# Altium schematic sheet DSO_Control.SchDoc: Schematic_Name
size A4; CompanyName: University of Melbourne; Engineer: Your Name Here; DocumentNumber: 1; Revision: 0.1; SheetNumber: 1; SheetTotal: 1; Title_Project: Project_Title; StudentNo: Student No.
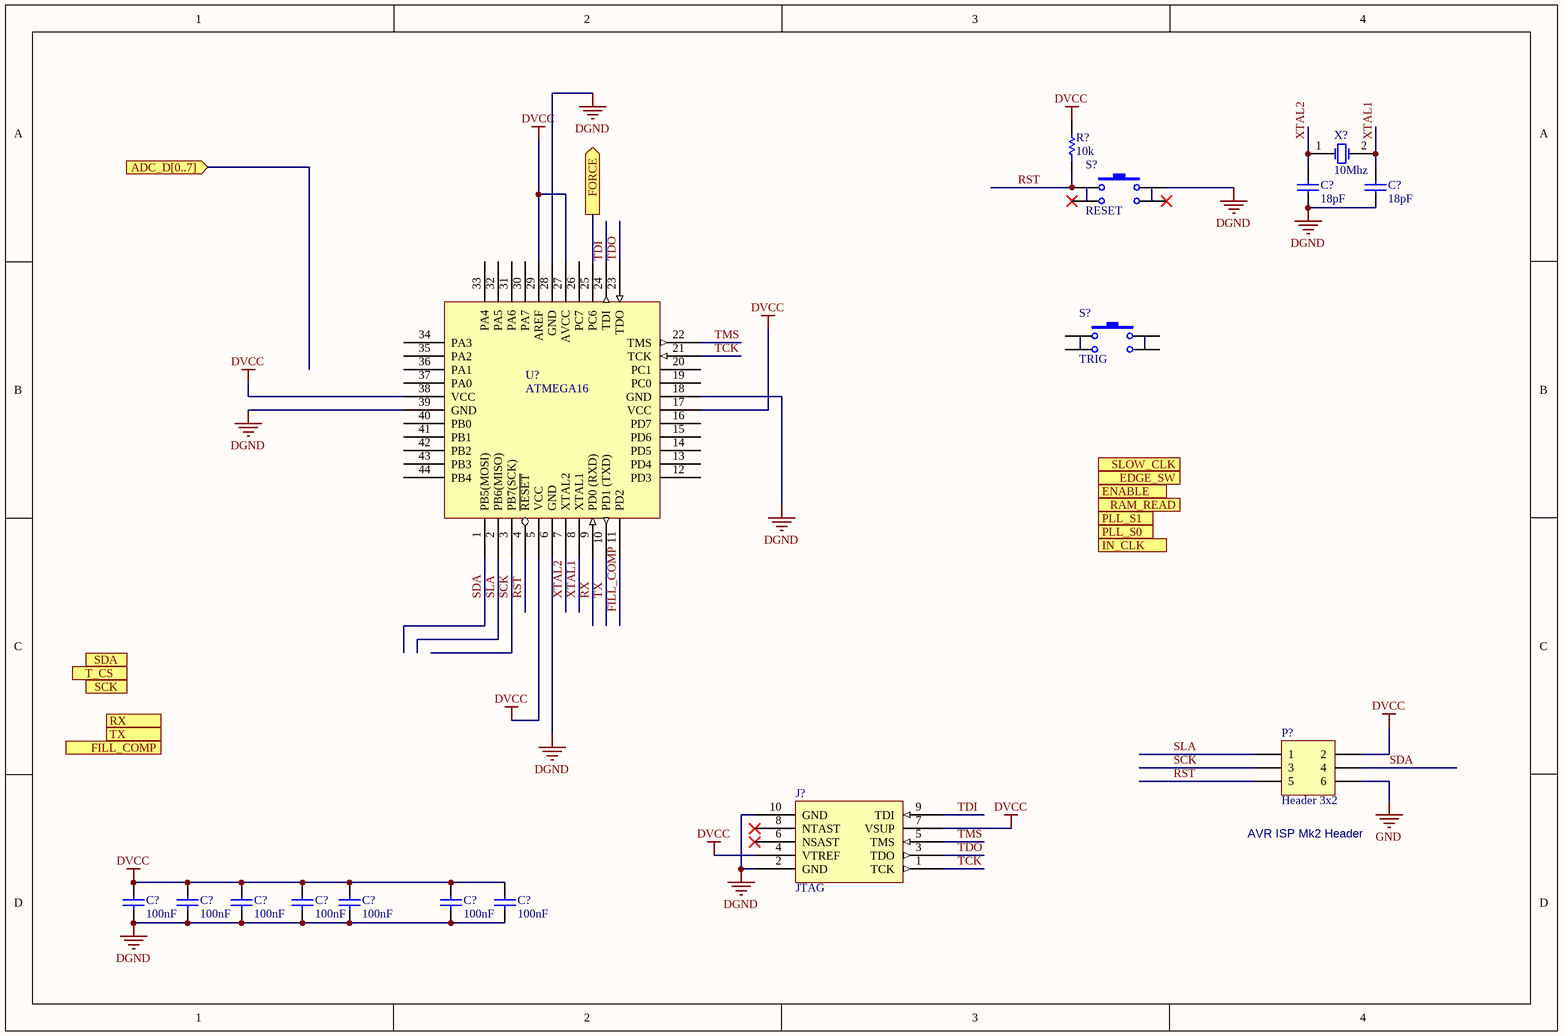
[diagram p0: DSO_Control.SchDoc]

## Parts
(Parts that share a designator on the sheet are numbered #1, #2 ... from top to bottom, then left to right.)
C?#1  18pF  [0805C]
C?#2  18pF  [0805C]
C?#3  100nF  [0805C]
C?#4  100nF  [0805C]
C?#5  100nF  [0805C]
C?#6  100nF  [0805C]
C?#7  100nF  [0805C]
C?#8  100nF  [0805C]
C?#9  100nF  [0805C]
J?  JTAG  [BOXEDVERT10]
P?  Header 3x2  [HDR3x2]
R?  10k  [0805]
S?#1  RESET  [SPST PB SWITCH SMD]
S?#2  TRIG  [SPST PB SWITCH SMD]
U?  ATMEGA16  [QFP-48]
X?  10Mhz  [XTAL_FLAT_SMD]

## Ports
ADC_D[0..7] (in), EDGE_SW (out), ENABLE (out), FILL_COMP (in), FORCE (out), IN_CLK (out), PLL_S0 (out), PLL_S1 (out), RAM_READ (out), RX (in), SCK (out), SDA (out), SLOW_CLK (out), T_CS (out), TX (out)

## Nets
DGND: C?#1.2 C?#2.2 C?#3.2 C?#4.2 C?#5.2 C?#6.2 C?#7.2 C?#8.2 C?#9.2 J?.2(GND) J?.10(GND) S?#1.2 U?.6(GND) U?.18(GND) U?.28(GND) U?.39(GND)
DVCC: C?#3.1 C?#4.1 C?#5.1 C?#6.1 C?#7.1 C?#8.1 C?#9.1 J?.4(VTREF) J?.7(VSUP) P?.2 R?.2 U?.5(VCC) U?.17(VCC) U?.27(AVCC) U?.29(AREF) U?.38(VCC)
GND: P?.6
FILL_COMP: U?.11(PD2)
FORCE: U?.25(PC6) ; port FORCE
RST: P?.5 R?.1 S?#1.1 U?.4(~{RESET})
RX: U?.9(PD0_(RXD))
SCK: P?.3 U?.3(PB7(SCK))
SDA: P?.4 U?.1(PB5(MOSI))
SLA: P?.1 U?.2(PB6(MISO))
TCK: J?.1(TCK) U?.21(TCK)
TDI: J?.9(TDI) U?.24(TDI)
TDO: J?.3(TDO) U?.23(TDO)
TMS: J?.5(TMS) U?.22(TMS)
TX: U?.10(PD1_(TXD))
XTAL1: C?#2.1 U?.8(XTAL1) X?.2(OSC2)
XTAL2: C?#1.1 U?.7(XTAL2) X?.1(OSC1)

Not connected (* = marked no-connect by the designer): J? 6(NSAST)* 8(NTAST)*; S?#1 3* 4*; S?#2 1 2 3 4; U? 12(PD3) 13(PD4) 14(PD5) 15(PD6) 16(PD7) 19(PC0) 20(PC1) 26(PC7) 30(PA7) 31(PA6) 32(PA5) 33(PA4) 34(PA3) 35(PA2) 36(PA1) 37(PA0) 40(PB0) 41(PB1) 42(PB2) 43(PB3) 44(PB4)

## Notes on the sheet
- (near P?) AVR ISP Mk2 Header

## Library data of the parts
C?#1-C?#9 = C: Capacitor; Reviewed by: RM - 2018/08/05
J? = JTAG_CON: Reviewed by: RM - 2018/08/05
P? = Header 3x2: Header, 5-Pin; Reviewed by: RM - 2018/08/05
R? = R: Resistor; Reviewed by: RM - 2018/08/05
S?#1 S?#2 = SW_PB_1P1T4: Momentary Push Button Switch 1P 1T 2pins; Reviewed by: RM - 2018/08/05
U? = ATMEGA16: ATMEGA16 Microcontroller; Reviewed by: RM - 2018/08/05
X? = XTAL: Crystal Oscillator; Reviewed by: RM - 2018/08/05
